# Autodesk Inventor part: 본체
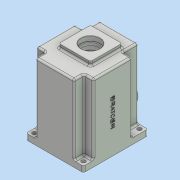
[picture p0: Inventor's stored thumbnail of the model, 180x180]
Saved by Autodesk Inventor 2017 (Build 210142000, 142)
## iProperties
Part Number: 본체
Material: 일반
Document SubType Name: Modeling
Designer: MRC
Density: 1 g/cm^3
Appearance: 기본값
Author: MRC
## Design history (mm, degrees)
sketch "스케치1"
  geometry: L1 (-33, -55)-(33, -55); L2 (33, -55)-(33, 55); L3 (33, 55)-(-33, 55); L4 (-33, 55)-(-33, -55); L5 (-33, -55)-(33, 55); L6 (33, -55)-(-33, 55); 1 further point
  constraints: 12 end point, 2 midpoint, 2 parallel, 1 horizontal, 1 perpendicular
  dimensions: "d0" = 66 distance of L3.end L2.end; "d1" = 110 distance of L2.end L1.end
extrude "돌출1" new body sketch "스케치1" distance "d2" = 130; taper "d3" = 0 deg
sketch "스케치2"
  geometry: L1 (-49, -38)-(49, -38); L2 (49, -38)-(49, 28); L3 (49, 28)-(-49, 28); L4 (-49, 28)-(-49, -38); L5 (-49, -38)-(49, 28); L6 (49, -38)-(-49, 28); L7 (-33, -55)-(33, -55) reference; 3 further points
  constraints: 12 end point, 3 midpoint, 2 parallel, 1 horizontal, 1 perpendicular, 1 vertical alignment
  dimensions: "d4" = 98 distance of L2.end L3.end; "d5" = 66 distance of L1.end L2.end; "d6" = 17 distance between parallel lines of L1 L7
extrude "돌출2" join sketch "스케치2" distance "d7" = 130; taper "d8" = 0 deg
sketch "스케치3"
  geometry: L1 (-49, -55)-(49, -55); L2 (49, -55)-(49, 55); L3 (49, 55)-(-49, 55); L4 (-49, 55)-(-49, -55); L5 (-49, -55)-(49, 55); L6 (49, -55)-(-49, 55); L7 (33, -55)-(-33, -55) reference; 3 further points
  constraints: 12 end point, 4 midpoint, 2 parallel, 1 horizontal, 1 perpendicular
  dimensions: "d9" = 98 distance of L3.end L2.end; "d10" = 110 distance of L2.end L1.end
extrude "돌출3" join sketch "스케치3" distance "d11" = 10; taper "d12" = 0 deg
node "작업 평면1"
sketch "스케치7"
  geometry: L1 (49, -55)-(-49, -55) reference; L2 (-26, 48)-(26, 48); L3 (-26, 48)-(-26, 31.729); L4 (26, 48)-(26, 31.729); A1 r 45 centre (0, -5) between (-26, 31.729) and (26, 31.729); 2 further points
  constraints: 6 end point, 2 point on circle, 2 vertical, 2 vertical alignment, 1 centre point, 1 horizontal, 1 midpoint
  dimensions: "d25" = 90 diameter of A1; "d26" = 50 distance from line of A1.centre L1; "d27" = 53 distance from line of A1.centre L2; "d28" = 52 distance of L2.start L2.end
extrude "돌출7" cut sketch "스케치7" distance "d29" = 9; taper "d30" = 0 deg
sketch "스케치13"
  geometry: L1 (-26, 48)-(26, 48) reference; L2 (-26, 31.729)-(-26, 48) reference; L3 (26, 48)-(26, 31.729) reference; L4 (-23, 30.143)-(-23, 45); L5 (-23, 45)-(23, 45); L6 (23, 45)-(23, 30.143); A1 r 45 centre (0, -5) between (-26, 31.729) and (26, 31.729) reference; A2 r 42 centre (0, -5) between (-23, 30.143) and (23, 30.143); 1 further point
  constraints: 6 end point, 2 point on circle, 1 centre point, 3 other
  dimensions: "d49" = 3 radial gap between concentric circles of A1 A2
extrude "돌출13" cut sketch "스케치13" distance "d50" = 112; taper "d51" = 0 deg
sketch "스케치14"
  geometry: L1 (49, -55)-(-49, -55) reference; C1 r 15 at (0, -25); C2 r 21 at (0, 6); 1 further point
  constraints: 2 centre point, 2 vertical alignment
  dimensions: "d52" = 30 diameter of C1; "d54" = 30 distance from line of C1.centre L1; "d55" = 42 diameter of C2; "d56" = 31 distance of C2.centre C1.centre
extrude "돌출14" join sketch "스케치14" distance "d57" = 7; taper "d58" = 0 deg
hole "구멍1" diameter "d61" = 19; stored, may be unused: countersink angle "d65" = 90 deg, drill point angle "d67" = 0 deg; dims "d62" = 6, "d63" = 22, "d64" = 7, "d66" = 10, "d68" = 10, "d69" = 10
sketch "스케치15"
  geometry: C1 r 17.5 at (0, 6); C2 r 11 at (0, -25) reference; A1 r 21 centre (0, 6) between (8.978, -12.984) and (-8.978, -12.984) reference; A2 r 15 centre (0, -25) between (-8.978, -12.984) and (8.978, -12.984) reference; 1 further point
  constraints: 1 centre point, 1 coincident
  dimensions: "d70" = 35 diameter of C1
extrude "돌출15" cut sketch "스케치15" distance "d71" = 10; taper "d72" = 0 deg
sketch "스케치16"
  geometry: L1 (-27, 33)-(27, 33); L2 (27, 33)-(27, -21); L3 (27, -21)-(-27, -21); L4 (-27, -21)-(-27, 33); L5 (-27, 33)-(27, -21); L6 (27, 33)-(-27, -21); A1 r 21 centre (0, 6) between (8.978, -12.984) and (-8.978, -12.984) reference; 4 further points
  constraints: 12 end point, 4 midpoint, 2 parallel, 1 coincident, 1 horizontal, 1 perpendicular, 1 vertical alignment
  dimensions: "d73" = 54 distance of L2.end L3.end; "d74" = 54 distance of L1.end L2.end
extrude "돌출16" join sketch "스케치16" distance "d75" = 7; taper "d76" = 0 deg
sketch "스케치17"
  geometry: L1 (27, 33)-(-27, 33) reference; L2 (-27, 33)-(-27, -21) reference; L3 (-27, -21)-(27, -21) reference; L4 (27, -21)-(27, 33) reference; C1 r 16 at (0, 6); 3 further points
  constraints: 2 midpoint, 1 centre point, 1 horizontal alignment, 1 vertical alignment
  dimensions: "d77" = 32 diameter of C1
extrude "돌출17" cut sketch "스케치17" distance "d78" = 8.3; taper "d79" = 0 deg
sketch "스케치18"
  geometry: C1 r 16 at (0, 0) reference; C2 r 14 at (0, 0); 1 further point
  constraints: 1 centre point, 1 coincident
  dimensions: "d80" = 28 diameter of C2
extrude "돌출18" cut sketch "스케치18" stored distance "d81" = 8.3; taper "d82" = 0 deg
sketch "스케치19"
  geometry: L1 (66, 0)-(0, 0) reference; L2 (-16, 130)-(82, 130) reference; C1 r 22.5 at (33, 90); 2 further points
  constraints: 1 centre point, 1 midpoint, 1 vertical alignment
  dimensions: "d83" = 45 diameter of C1; "d84" = 40 distance from line of C1.centre L2
extrude "돌출19" join sketch "스케치19" distance "d85" = 10; taper "d86" = 0 deg
sketch "스케치20"
  geometry: L1 (66, 0)-(0, 0) reference; C1 r 15 at (33, 41); C2 r 22.5 at (33, 90) reference; 2 further points
  constraints: 1 centre point, 1 midpoint, 1 vertical alignment
  dimensions: "d87" = 30 diameter of C1; "d88" = 49 distance of C1.centre C2.centre
extrude "돌출20" join sketch "스케치20" distance "d89" = 5; taper "d90" = 0 deg
sketch "스케치21"
  geometry: C1 r 10 at (0, 0); C2 r 15 at (0, 0) reference; 1 further point
  constraints: 1 centre point, 1 concentric
  dimensions: "d91" = 20 diameter of C1
extrude "돌출21" cut sketch "스케치21" stored distance "d92" = 5; taper "d93" = 0 deg
sketch "스케치22"
  geometry: C1 r 15 at (23, 80); C2 r 10 at (23, 80) reference; 1 further point
  constraints: 1 centre point, 1 concentric
  dimensions: "d94" = 30 diameter of C1
extrude "돌출22" cut sketch "스케치22" distance "d95" = 5; taper "d96" = 0 deg
hole "구멍2" diameter "d99" = 33.376; stored, may be unused: countersink angle "d103" = 90 deg, drill point angle "d105" = 118 deg; dims "d97" = 10, "d98" = 10, "d100" = 30, "d101" = 35, "d102" = 10, "d104" = 77.3
sketch "스케치23"
  geometry: L1 (49, 55)-(-49, 55) reference; L2 (-49, 55)-(-49, -55) reference; L3 (49, -55)-(49, 55) reference; L4 (49, -55)-(-49, -55) reference; C1 r 3.5 at (-42, 48); C2 r 3.5 at (-42, -48); C3 r 3.5 at (42, -48); C4 r 3.5 at (42, 48); 1 further point
  constraints: 4 centre point
  dimensions: "d106" = 7 diameter of C1; "d107" = 7 distance from line of C1.centre L1; "d108" = 7 distance from line of C1.centre L2; "d109" = 7 diameter of C2; "d110" = 7 diameter of C3; "d111" = 7 diameter of C4; "d113" = 84 distance of C4.centre C1.centre; "d114" = 96 distance of C3.centre C4.centre; "d115" = 96 distance of C2.centre C1.centre; "d116" = 7 distance from line of C2.centre L2; "d117" = 7 distance from line of L3 C3.centre; "d118" = 7 distance from line of L4 C3.centre
extrude "돌출23" cut sketch "스케치23" stored distance "d119" = 5; taper "d120" = 0 deg
sketch "스케치24"
  geometry: L1 (49, -55)-(-49, -55) reference; L2 (23, 45)-(23, 30.143) reference; L3 (-23, 45)-(23, 45) reference; L4 (-23, 30.143)-(-23, 45) reference; L5 (36, -1)-(41.809, -1); L6 (36, -9)-(41.809, -9); L7 (-36, -1)-(-41.809, -1); L8 (-36, -9)-(-41.809, -9); A1 r 36 centre (0, -5) between (36, -5) and (-36, -5); A2 r 4 centre (36, -5) between (36, -1) and (36, -9); A3 r 4 centre (-36, -5) between (-36, -9) and (-36, -1); A4 r 21 centre (0, 6) between (8.978, -12.984) and (-8.978, -12.984) reference; A5 r 15 centre (0, -25) between (-8.978, -12.984) and (8.978, -12.984) reference; A6 r 42 centre (0, -5) between (-23, 30.143) and (23, 30.143) reference; 1 further point
  constraints: 10 point on circle, 8 end point, 4 horizontal, 4 tangent, 3 centre point, 1 vertical alignment
  dimensions: "d121" = 72 diameter of A1; "d122" = 50 distance from line of A1.centre L1; "d123" = 8 diameter of A2; "d124" = 8 diameter of A3; "d125" = 11 vertical distance of A1.start A4.centre; "d126" = 11 vertical distance of A1.end A4.centre
extrude "돌출24" join sketch "스케치24" stored distance "d127" = 5; taper "d128" = 0 deg
fillet "모깎기1" dims "d129" = 3
fillet "모깎기2" dims "d130" = 3
sketch "스케치25"
  geometry: L1 (23, 45)-(23, 30.143) reference; L2 (38.367, -1)-(36, -1) reference; L3 (36, -9)-(38.367, -9) reference; L4 (-38.367, -9)-(-36, -9) reference; L5 (-36, -1)-(-38.367, -1) reference; L6 (-23, 30.143)-(-23, 45) reference; L7 (-23, 45)-(23, 45) reference; L8 (-26, 48)-(26, 48) reference; L9 (-26, 31.729)-(-26, 48) reference; L10 (26, 48)-(26, 31.729) reference; A1 r 42 centre (0, -5) between (41.318, 2.538) and (23, 30.143) reference; A2 r 3 centre (38.367, 2) between (38.367, -1) and (41.318, 2.538) reference; A3 r 4 centre (36, -5) between (36, -1) and (36, -9) reference; A4 r 3 centre (38.367, -12) between (41.318, -12.538) and (38.367, -9) reference; A5 r 42 centre (0, -5) between (-41.318, -12.538) and (41.318, -12.538) reference; A6 r 3 centre (-38.367, -12) between (-38.367, -9) and (-41.318, -12.538) reference; A7 r 4 centre (-36, -5) between (-36, -9) and (-36, -1) reference; A8 r 3 centre (-38.367, 2) between (-41.318, 2.538) and (-38.367, -1) reference; A9 r 42 centre (0, -5) between (-23, 30.143) and (-41.318, 2.538) reference; A10 r 45 centre (0, -5) between (-26, 31.729) and (26, 31.729) reference; 3 further points
  constraints: 2 coincident
hole "구멍3" sketch "스케치25" at (-36, -5), (36, -5) diameter "d131" = 3.242; stored, may be unused: countersink angle "d135" = 90 deg, drill point angle "d137" = 118 deg; dims "d132" = 7, "d133" = 35, "d134" = 10, "d136" = 9
fillet "모깎기3" dims "d138" = 3
fillet "모깎기4" dims "d139" = 3
fillet "모깎기5" dims "d140" = 3
fillet "모깎기6" dims "d141" = 3
fillet "모깎기7" dims "d142" = 3
fillet "모깎기8" dims "d143" = 3
fillet "모깎기9" dims "d144" = 6
fillet "모깎기10" dims "d145" = 3
fillet "모깎기11" dims "d146" = 3
fillet "모깎기12" dims "d147" = 3
chamfer "모따기1" distance "d148" = 1; stored, may be unused: second distance "d149" = 2, angle "d150" = 45 deg
fillet "모깎기13" dims "d151" = 3
chamfer "모따기2" distance "d152" = 0.8; stored, may be unused: second distance "d153" = 2, angle "d154" = 30 deg
fillet "모깎기14" dims "d155" = 0.3
sketch "스케치26"
  geometry: L1 (-130, 107)-(-130, 86) reference; L2 (-13, 83)-(-127, 83) reference; 2 further points
  constraints: 1 other
  dimensions: "d156" = 65 distance from line of point (-65, 50) L1; "d157" = 33 distance from line of point (-65, 50) L2
feature "엠보싱1" sketch "스케치26" dims "d158" = 0.5, "d159" = 0
fillet "모깎기15" dims "d160" = 3
fillet "모깎기16" dims "d161" = 3
fillet "모깎기17" dims "d162" = 0.3
node "솔리드1"
node "투영된 루프5"
node "투영된 루프6"
node "투영된 루프7"
node "투영된 루프8"
node "투영된 루프9"
node "투영된 루프10"
node "투영된 루프11"
